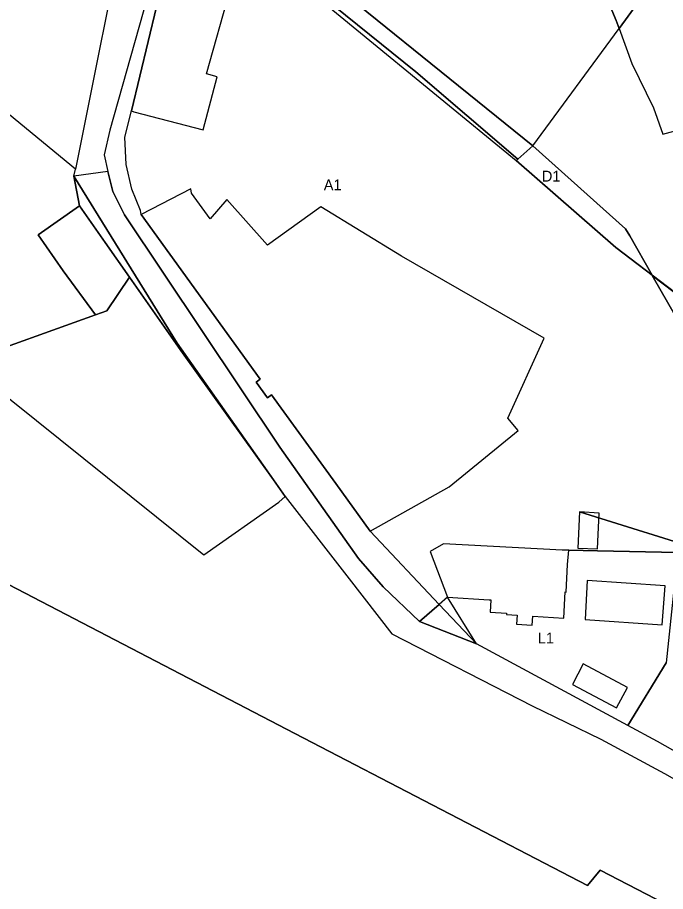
# Model space of a CAD drawing. Extents: x -749314 to -746497, y -1026537 to -1024935.
# Drawn here: x -747475.9 to -747327.2, y -1025726.2 to -1025525.6 of the extents above; entities that cross this region are included whole.
import ezdxf

# ---------------------------------------------------------------- set-up
doc = ezdxf.new("R2010")
doc.units = 0
for name, color, linetype in [('Default', 7, 'Continuous'), ('K_CD1', 7, 'Continuous'), ('K_DOCD2', 7, 'Continuous'), ('K_DOSZDC1', 7, 'Continuous'), ('K_JVL', 7, 'Continuous'), ('K_NH_SZDC', 7, 'Continuous'), ('K_SZDC1', 7, 'Continuous')]:
    doc.layers.add(name, color=color, linetype=linetype)

msp = doc.modelspace()

# ---------------------------------------------------------------- linework, layer by layer
at = {"layer": 'Default'}
msp.add_lwpolyline([(-747333.7, -1025522.43), (-747337.88, -1025528.12), (-747334.95, -1025536.15), (-747329.97, -1025546.35), (-747327.84, -1025552.37), (-747323.35, -1025551.14)], dxfattribs=at)
for points in [[(-747357.69, -1025555.06), (-747337.88, -1025528.12), (-747334.95, -1025536.15), (-747329.97, -1025546.35), (-747327.84, -1025552.37), (-747323.35, -1025551.14), (-747314.62, -1025580.82), (-747306.89, -1025602.7), (-747306.8, -1025602.91), (-747309.47, -1025600.54), (-747330.28, -1025584.74), (-747335.45, -1025575.7), (-747336.38, -1025574.1)], [(-747330.25, -1025584.76), (-747309.47, -1025600.54), (-747306.8, -1025602.91), (-747302.37, -1025613.46), (-747294.18, -1025630.48), (-747302.96, -1025632.32)]]:
    msp.add_lwpolyline(points, close=True, dxfattribs=at)
at = {"layer": 'K_CD1'}
for points in [[(-747439.45, -1025497.23), (-747454.72, -1025551.44), (-747456, -1025557.11), (-747455.21, -1025560.92), (-747454.06, -1025565.5), (-747451.38, -1025570.91), (-747415.7, -1025624.23), (-747397.7, -1025649.74), (-747392, -1025656.27), (-747383.69, -1025664.23), (-747379.14, -1025660.28), (-747394.96, -1025643.45), (-747402.88, -1025632.57), (-747417.61, -1025612.17), (-747418.58, -1025612.87), (-747421.18, -1025609.27), (-747420.21, -1025608.56), (-747447.5, -1025570.77), (-747447.7, -1025569.85), (-747449.66, -1025564.99), (-747450.96, -1025559.34), (-747451.26, -1025553.08), (-747449.79, -1025546.98), (-747442.08, -1025515.07)], [(-747434.61, -1025498.37), (-747361.5, -1025558.41), (-747338.64, -1025578.39), (-747309.47, -1025600.54), (-747330.25, -1025584.76), (-747302.96, -1025632.32)], [(-747324.44, -1025648.39), (-747342.85, -1025647.99), (-747349.43, -1025647.85), (-747350.95, -1025647.81), (-747378.14, -1025646.36), (-747381.26, -1025648.11), (-747377.22, -1025658.62), (-747379.14, -1025660.28), (-747394.96, -1025643.45), (-747376.84, -1025633.33), (-747361.01, -1025620.39), (-747363.43, -1025617.53), (-747355.09, -1025599.16), (-747387.84, -1025580.35), (-747406.32, -1025569.03), (-747418.55, -1025577.83), (-747427.9, -1025567.32), (-747431.73, -1025571.76), (-747435.95, -1025565.91), (-747436.11, -1025564.92), (-747447.5, -1025570.77), (-747447.7, -1025569.85), (-747449.66, -1025564.99), (-747450.96, -1025559.34), (-747451.26, -1025553.08), (-747449.79, -1025546.98), (-747449.22, -1025547.23), (-747433.31, -1025551.36), (-747430.08, -1025539.18), (-747432.54, -1025538.52), (-747427.08, -1025519.14)], [(-747316.56, -1025648.56), (-747346.98, -1025639.05), (-747347.38, -1025647.34), (-747342.84, -1025647.55), (-747342.47, -1025639.31), (-747346.98, -1025639.05), (-747316.56, -1025648.56)]]:
    msp.add_lwpolyline(points, dxfattribs=at)
for points in [[(-747361.12, -1025558.08), (-747384.53, -1025538.06), (-747419.14, -1025510.09), (-747434.61, -1025498.37), (-747361.5, -1025558.41)], [(-747442.08, -1025515.07), (-747449.79, -1025546.98), (-747449.22, -1025547.23), (-747433.31, -1025551.36), (-747430.08, -1025539.18), (-747432.54, -1025538.52), (-747427.08, -1025519.14), (-747427.25, -1025515.55), (-747428.21, -1025512.95), (-747429.68, -1025510.41), (-747432.47, -1025507.47), (-747438.47, -1025505.31), (-747438.78, -1025506.15)], [(-747330.28, -1025584.74), (-747338.64, -1025578.39), (-747361.5, -1025558.41), (-747361.12, -1025558.08), (-747357.69, -1025555.06), (-747336.38, -1025574.1), (-747335.45, -1025575.7)], [(-747383.69, -1025664.23), (-747392, -1025656.27), (-747397.7, -1025649.74), (-747415.7, -1025624.23), (-747451.38, -1025570.91), (-747454.06, -1025565.5), (-747455.21, -1025560.92), (-747462.97, -1025562), (-747439.26, -1025600.34), (-747417.19, -1025631.71), (-747414.46, -1025635.53), (-747399.81, -1025654.4), (-747390.04, -1025667.02), (-747357.84, -1025683.59), (-747342.1, -1025691.24), (-747327.46, -1025699.06), (-747309.33, -1025709.32), (-747309.7, -1025704.76), (-747316.22, -1025698.99), (-747329.04, -1025691.76), (-747335.84, -1025688.09), (-747370.63, -1025669.34)], [(-747431.73, -1025571.76), (-747435.95, -1025565.91), (-747436.11, -1025564.92), (-747447.5, -1025570.77), (-747420.21, -1025608.56), (-747421.18, -1025609.27), (-747418.58, -1025612.87), (-747417.61, -1025612.17), (-747402.88, -1025632.57), (-747394.96, -1025643.45), (-747376.84, -1025633.33), (-747361.01, -1025620.39), (-747363.43, -1025617.53), (-747355.09, -1025599.16), (-747387.84, -1025580.35), (-747406.32, -1025569.03), (-747418.55, -1025577.83), (-747427.9, -1025567.32)], [(-747457.99, -1025593.85), (-747455.4, -1025592.92), (-747450.21, -1025585.21), (-747455.81, -1025577.21), (-747461.72, -1025568.8), (-747471.2, -1025575.47), (-747465.41, -1025583.71)], [(-747346.98, -1025639.05), (-747347.38, -1025647.34), (-747342.84, -1025647.55), (-747342.47, -1025639.31)], [(-747349.43, -1025647.85), (-747350.95, -1025647.81), (-747378.14, -1025646.36), (-747381.26, -1025648.11), (-747377.22, -1025658.62), (-747367.72, -1025659.21), (-747367.27, -1025659.23), (-747367.45, -1025662.07), (-747363.7, -1025662.32), (-747363.72, -1025662.57), (-747361.25, -1025662.73), (-747361.39, -1025664.78), (-747357.81, -1025665.02), (-747357.67, -1025662.96), (-747350.59, -1025663.43), (-747350.24, -1025657.43), (-747350.04, -1025657.44), (-747349.68, -1025651.14)], [(-747349.43, -1025647.85), (-747342.85, -1025647.99), (-747324.44, -1025648.39), (-747324.49, -1025648.86), (-747327.06, -1025673.68), (-747335.84, -1025688.09), (-747370.63, -1025669.34), (-747377.22, -1025658.62), (-747367.72, -1025659.21), (-747367.27, -1025659.23), (-747367.45, -1025662.07), (-747363.7, -1025662.32), (-747363.72, -1025662.57), (-747361.25, -1025662.73), (-747361.39, -1025664.78), (-747357.81, -1025665.02), (-747357.67, -1025662.96), (-747350.59, -1025663.43), (-747350.24, -1025657.43), (-747350.04, -1025657.44), (-747349.68, -1025651.14)], [(-747345.68, -1025663.71), (-747327.96, -1025664.97), (-747327.33, -1025656.03), (-747345.17, -1025654.82)], [(-747345.68, -1025663.71), (-747327.96, -1025664.97), (-747327.33, -1025656.03), (-747345.17, -1025654.82)], [(-747377.22, -1025658.62), (-747379.14, -1025660.28), (-747370.63, -1025669.34)], [(-747370.63, -1025669.34), (-747379.14, -1025660.28), (-747383.69, -1025664.23)], [(-747338.48, -1025684.03), (-747335.96, -1025679.34), (-747346.11, -1025673.89), (-747348.56, -1025678.66)], [(-747338.48, -1025684.03), (-747335.96, -1025679.34), (-747346.11, -1025673.89), (-747348.56, -1025678.66)]]:
    msp.add_lwpolyline(points, close=True, dxfattribs=at)
at = {"layer": 'K_DOCD2'}
msp.add_lwpolyline([(-747439.26, -1025600.34), (-747462.97, -1025562), (-747461.72, -1025568.8), (-747455.81, -1025577.21), (-747450.21, -1025585.21), (-747438.45, -1025601.99), (-747417.19, -1025631.71)], close=True, dxfattribs=at)
at = {"layer": 'K_DOSZDC1'}
for points in [[(-747321.09, -1025732.24), (-747342.19, -1025721.29), (-747345.16, -1025724.81), (-747412.27, -1025689.89), (-747594.31, -1025595.17), (-747645.99, -1025568.28), (-747732.3, -1025526.84)], [(-747732.3, -1025526.84), (-747645.99, -1025568.28), (-747594.31, -1025595.17), (-747412.27, -1025689.89), (-747345.16, -1025724.81), (-747342.19, -1025721.29), (-747321.09, -1025732.24), (-747317.29, -1025742.74), (-747247.64, -1025780.1), (-747222.79, -1025794.6), (-747071.27, -1025869.13), (-747036.19, -1025887.86), (-747009.36, -1025903.18), (-746982.11, -1025915.51), (-746931.03, -1025940.57), (-746888.2, -1025982.16)], [(-747488.27, -1025604.69), (-747433.17, -1025648.92), (-747415.97, -1025636.78), (-747414.46, -1025635.53), (-747399.81, -1025654.4), (-747390.04, -1025667.02), (-747357.84, -1025683.59), (-747342.1, -1025691.24), (-747327.46, -1025699.06), (-747309.33, -1025709.32)], [(-747316.22, -1025698.99), (-747329.04, -1025691.76), (-747335.84, -1025688.09), (-747327.06, -1025673.68)]]:
    msp.add_lwpolyline(points, dxfattribs=at)
at = {"layer": 'K_JVL'}
for points in [[(-747544.01, -1025501.28), (-747514.17, -1025471.87), (-747501.71, -1025459.59), (-747450.27, -1025498.83), (-747462.57, -1025560.41), (-747480.42, -1025545.81), (-747535.25, -1025507.41)], [(-747507.44, -1025587.57), (-747488.27, -1025604.69), (-747457.99, -1025593.85), (-747465.41, -1025583.71), (-747471.2, -1025575.47), (-747461.72, -1025568.8), (-747462.97, -1025562), (-747462.57, -1025560.41), (-747480.42, -1025545.81), (-747493.86, -1025567.55), (-747495.01, -1025569.25)], [(-747457.99, -1025593.85), (-747488.27, -1025604.69), (-747433.17, -1025648.92), (-747415.97, -1025636.78), (-747414.46, -1025635.53), (-747417.19, -1025631.71), (-747438.45, -1025601.99), (-747450.21, -1025585.21), (-747455.4, -1025592.92)]]:
    msp.add_lwpolyline(points, close=True, dxfattribs=at)
at = {"layer": 'K_NH_SZDC'}
for points in [[(-747357.69, -1025555.06), (-747336.38, -1025574.1), (-747335.45, -1025575.7), (-747330.28, -1025584.74)], [(-747330.25, -1025584.76), (-747302.96, -1025632.32), (-747296.55, -1025643.69), (-747302.27, -1025644.22), (-747310.5, -1025644.98), (-747316.48, -1025646.44), (-747324.44, -1025648.39)]]:
    msp.add_lwpolyline(points, dxfattribs=at)
at = {"layer": 'K_SZDC1'}
for points in [[(-747345.33, -1025509.89), (-747385.57, -1025466.49), (-747386.44, -1025465.56), (-747395.49, -1025477.61), (-747416.82, -1025507.19), (-747357.69, -1025555.06), (-747337.88, -1025528.12), (-747338.55, -1025526.3)], [(-747357.69, -1025555.06), (-747416.82, -1025507.19), (-747418.18, -1025508.87), (-747436.18, -1025494.75), (-747434.61, -1025498.37), (-747419.14, -1025510.09), (-747384.53, -1025538.06), (-747361.12, -1025558.08)], [(-747337.88, -1025528.12), (-747333.7, -1025522.43), (-747345.33, -1025509.89), (-747338.55, -1025526.3)]]:
    msp.add_lwpolyline(points, close=True, dxfattribs=at)

# ---------------------------------------------------------------- texts
for s, p in [('D1', (-747355.6, -1025563.25)), ('A1', (-747405.64, -1025565.25)), ('L1', (-747356.54, -1025669.25))]:
    msp.add_text(s, height=2.5).set_placement(p)

doc.saveas('drawing.dxf')
